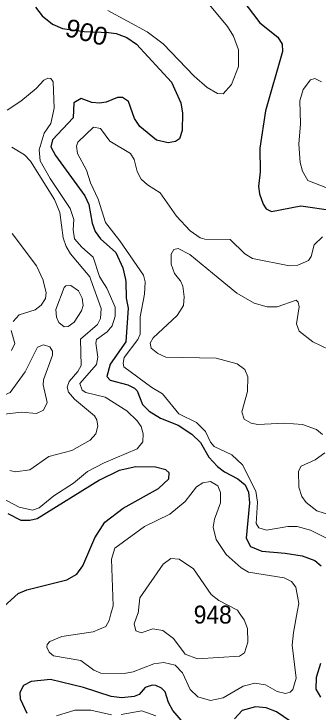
# Model space of a CAD drawing. Extents: x 473.9 to 500, y 7733.1 to 7760.8.
# Drawn here: x 486.645 to 488.002, y 7749.235 to 7752.349 of the extents above; entities that cross this region are included whole.
import ezdxf
from ezdxf.enums import TextEntityAlignment as Align

# ---------------------------------------------------------------- set-up
doc = ezdxf.new("R2010")
doc.units = 0
doc.header["$LTSCALE"] = 0.032
doc.layers.add('1', color=7, linetype='Continuous', lineweight=25)
doc.layers.add('2', color=7, linetype='Continuous', lineweight=13)
doc.layers.add('21', color=7, linetype='Continuous')
doc.layers.add('61', color=7, linetype='Continuous')

msp = doc.modelspace()

# ---------------------------------------------------------------- linework, layer by layer
at = {"layer": '1'}
for points in [[(487.6624, 7752.4168), (487.7421, 7752.3088), (487.8228, 7752.245), (487.8424, 7752.2149), (487.8435, 7752.1809), (487.7675, 7751.9168), (487.7416, 7751.7506), (487.7432, 7751.6445), (487.7368, 7751.5795), (487.7412, 7751.546), (487.7566, 7751.5003), (487.7708, 7751.4799), (487.7935, 7751.4682), (487.9246, 7751.4925), (488.0693, 7751.4728)], [(486.7413, 7752.3792), (486.7715, 7752.3404)], [(486.7715, 7752.3404), (486.8178, 7752.3038), (486.8624, 7752.2837), (486.9592, 7752.27), (487.0341, 7752.2684), (487.0669, 7752.2669), (487.1013, 7752.2616), (487.1494, 7752.2436), (487.1916, 7752.2137), (487.3483, 7752.0443), (487.3892, 7751.9522), (487.3974, 7751.9065), (487.396, 7751.8291), (487.384, 7751.7921), (487.3653, 7751.7804), (487.3331, 7751.774), (487.281, 7751.7862), (487.2073, 7751.8476), (487.1834, 7751.883), (487.1561, 7751.9579), (487.1295, 7751.9762), (487.1077, 7751.9757), (487.0572, 7751.9558), (487.0267, 7751.9508), (486.9933, 7751.9535), (486.9448, 7751.9715), (486.9128, 7751.953), (486.9101, 7751.885), (486.8175, 7751.7871), (486.8101, 7751.7566), (486.8313, 7751.7171), (486.9619, 7751.5371), (486.9793, 7751.4997), (486.9944, 7751.416), (487.0074, 7751.378), (487.0312, 7751.3459), (487.0992, 7751.2845), (487.1316, 7751.217), (487.1427, 7751.1649), (487.145, 7751.154), (487.1466, 7751.0807), (487.1546, 7751.0366), (487.1447, 7750.8865), (487.0745, 7750.7865), (487.06, 7750.7324), (487.0744, 7750.716), (487.1527, 7750.694), (487.1835, 7750.6796), (487.195, 7750.6677), (487.218, 7750.6067), (487.2485, 7750.5774), (487.2991, 7750.5462), (487.3771, 7750.5153), (487.4395, 7750.4738), (487.4778, 7750.4368), (487.5141, 7750.3725), (487.5532, 7750.3299), (487.5851, 7750.3061), (487.644, 7750.2749), (487.6765, 7750.2486), (487.6914, 7750.2158), (487.6958, 7750.1679), (487.6811, 7750.0111), (487.701, 7749.973), (487.7509, 7749.9518), (487.8557, 7749.9439), (487.931, 7749.9316), (487.9871, 7749.9104), (488.0151, 7749.8877)], [(486.6007, 7749.7061), (486.6635, 7749.7638), (486.7032, 7749.7805), (486.8809, 7749.8243), (486.9263, 7749.8499), (486.9528, 7749.887), (487.0065, 7750.0119), (487.0514, 7750.0819), (487.1322, 7750.1441), (487.2902, 7750.2322), (487.3363, 7750.2745), (487.337, 7750.3026), (487.3233, 7750.3147), (487.2769, 7750.3266), (487.1884, 7750.3282), (487.1141, 7750.3124), (487.0273, 7750.2693), (486.7481, 7750.0969), (486.7167, 7750.0894), (486.6774, 7750.0889), (486.6192, 7750.1185)], [(488.0124, 7749.4521), (487.9937, 7749.3883), (487.9924, 7749.3375), (488.0129, 7749.3011)], [(487.3201, 7749.325), (487.3042, 7749.3409), (487.2789, 7749.3539), (487.2613, 7749.3543), (487.2311, 7749.3439), (487.2032, 7749.3134), (487.1819, 7749.304), (487.1261, 7749.2984), (487.0795, 7749.3043), (486.9558, 7749.344), (486.8089, 7749.3803), (486.7227, 7749.3716), (486.6884, 7749.3525), (486.6715, 7749.3218), (486.6724, 7749.2932), (486.7028, 7749.2292)], [(487.401, 7749.1867), (487.3545, 7749.2411), (487.3351, 7749.2771), (487.3201, 7749.325)], [(487.9893, 7749.1176), (487.8171, 7749.2364), (487.7705, 7749.2541), (487.7232, 7749.2574), (487.663, 7749.2419), (487.6289, 7749.2052)]]:
    msp.add_lwpolyline(points, dxfattribs=at)
at = {"layer": '2'}
for points in [[(487.0643, 7752.3643), (487.2396, 7752.2688), (487.3115, 7752.2161), (487.4499, 7752.072), (487.5069, 7752.0209), (487.553, 7751.9937), (487.5784, 7751.9923), (487.6153, 7752.0339), (487.6475, 7752.114), (487.6468, 7752.1892), (487.6245, 7752.2492), (487.5973, 7752.293), (487.5029, 7752.4077)], [(486.6157, 7751.9203), (486.6753, 7751.9597), (486.7444, 7752.0166), (486.7788, 7752.0532), (486.796, 7752.0625), (486.8103, 7752.0615), (486.8201, 7752.0464), (486.825, 7751.9282), (486.8102, 7751.8596), (486.7795, 7751.8171), (486.7583, 7751.7421), (486.7616, 7751.6943), (486.8063, 7751.6155), (486.8965, 7751.4805), (486.9126, 7751.4317), (486.9095, 7751.386), (486.9157, 7751.3459), (486.9481, 7751.3082), (486.9986, 7751.2641), (487.0274, 7751.1772), (487.036, 7751.1631), (487.0589, 7751.1252), (487.0967, 7751.0409), (487.0975, 7751.0008), (487.0833, 7750.9584), (487.0607, 7750.9316), (487.0142, 7750.8964), (487.0109, 7750.8798), (487.0197, 7750.8177), (487.0136, 7750.7853), (486.9394, 7750.7001), (486.9489, 7750.6713), (486.9654, 7750.6597), (487.0523, 7750.64), (487.1491, 7750.5791), (487.1952, 7750.5345), (487.2127, 7750.5089), (487.2224, 7750.4753), (487.2195, 7750.4398), (487.1948, 7750.4084)], [(488.0366, 7751.5745), (487.9558, 7751.6067), (487.9323, 7751.648), (487.9216, 7751.6857), (487.9161, 7751.7688), (487.9242, 7751.8594), (487.9211, 7751.9608), (487.9355, 7752.0116), (487.968, 7752.0551), (487.9871, 7752.0607), (488.0166, 7752.046)], [(488.0218, 7751.3546), (487.9852, 7751.3183), (487.971, 7751.2668), (487.9595, 7751.2488), (487.9115, 7751.2278), (487.8745, 7751.2255), (487.71, 7751.2575), (487.6757, 7751.2788), (487.6098, 7751.3422), (487.4972, 7751.3446), (487.4756, 7751.3499), (487.4307, 7751.3813), (487.371, 7751.4474), (487.2978, 7751.5503), (487.2403, 7751.5862), (487.2121, 7751.6119), (487.1945, 7751.6455), (487.1819, 7751.6992), (487.1655, 7751.7268), (487.0737, 7751.782), (487.0315, 7751.8373), (487.0008, 7751.8439), (486.9296, 7751.7765), (486.9239, 7751.7599), (486.9292, 7751.7259), (486.9689, 7751.6525), (486.9871, 7751.5952)], [(486.6271, 7750.3125), (486.6524, 7750.3058), (486.7156, 7750.3155), (486.8014, 7750.3751), (486.9028, 7750.402), (486.9851, 7750.447), (487.0112, 7750.4763), (487.0199, 7750.5108), (487.0152, 7750.5391), (487.005, 7750.5566), (486.9149, 7750.6307), (486.889, 7750.6614), (486.8831, 7750.6843), (486.8909, 7750.71), (486.9307, 7750.7533), (486.9451, 7750.7803), (486.9425, 7750.8988), (487.0184, 7750.9632), (487.0321, 7750.9907), (487.0348, 7751.035), (486.9887, 7751.1623), (486.9836, 7751.1764), (486.8982, 7751.2795), (486.8782, 7751.3118), (486.8651, 7751.3497), (486.8499, 7751.4627), (486.8266, 7751.5206), (486.7191, 7751.6922), (486.6922, 7751.7205), (486.6357, 7751.7544)], [(486.9871, 7751.5952), (487.0206, 7751.5233), (487.0531, 7751.4183), (487.1181, 7751.3362), (487.2231, 7751.1839), (487.2278, 7751.1663), (487.231, 7751.1541), (487.2279, 7751.0983), (487.2089, 7750.9975), (487.2083, 7750.921), (487.1976, 7750.8967), (487.1376, 7750.8161), (487.1322, 7750.7912), (487.1356, 7750.7746), (487.2599, 7750.6827), (487.3079, 7750.6543), (487.3815, 7750.5646), (487.4602, 7750.5268), (487.5004, 7750.4867), (487.5216, 7750.439), (487.5387, 7750.4196), (487.6178, 7750.3821), (487.6652, 7750.3371), (487.725, 7750.2202), (487.732, 7750.171), (487.7256, 7750.0758), (487.7379, 7750.0563), (487.7716, 7750.0469), (487.867, 7750.0629), (487.9088, 7750.0629), (487.9677, 7750.0462), (488.036, 7750.0126)], [(486.6372, 7751.37), (486.7462, 7751.2248), (486.7757, 7751.1609), (486.7762, 7751.1587), (486.7889, 7751.1063), (486.7856, 7751.0795), (486.7669, 7751.0492), (486.7396, 7751.0295), (486.6678, 7751.0064), (486.6412, 7750.9767)], [(488.0215, 7750.4724), (487.9952, 7750.495), (487.9319, 7750.5171), (487.8525, 7750.5236), (487.7325, 7750.5173), (487.7042, 7750.524), (487.6716, 7750.5412), (487.6622, 7750.5746), (487.6877, 7750.6651), (487.6893, 7750.7295), (487.6755, 7750.7633), (487.6405, 7750.7889), (487.5481, 7750.8139), (487.3235, 7750.8173), (487.2869, 7750.8336), (487.2569, 7750.8586), (487.2535, 7750.8804), (487.2661, 7750.9042), (487.373, 7751.0033), (487.4018, 7751.0478), (487.4047, 7751.087), (487.3982, 7751.1347), (487.3878, 7751.1588), (487.3798, 7751.1689), (487.3619, 7751.1915), (487.3465, 7751.2329), (487.3471, 7751.2779), (487.3586, 7751.2979), (487.3778, 7751.3024), (487.4296, 7751.2762), (487.5559, 7751.1719), (487.6389, 7751.1034), (487.717, 7751.0586), (487.7748, 7751.0431), (487.8199, 7751.0431), (487.904, 7751.0723), (487.9126, 7751.0639), (487.9175, 7751.042), (487.9064, 7750.9659), (487.9178, 7750.9339), (487.9789, 7750.8865), (488.09, 7750.8334)], [(486.6321, 7750.9364), (486.6496, 7750.8785), (486.6348, 7750.848)], [(487.1948, 7750.4084), (487.0475, 7750.3462), (486.9741, 7750.3078), (486.9108, 7750.2553), (486.823, 7750.1993), (486.7571, 7750.1454), (486.7281, 7750.1355), (486.6678, 7750.1485), (486.563, 7750.2037), (486.4527, 7750.3122), (486.3765, 7750.3667), (486.2912, 7750.3863), (486.2585, 7750.4055), (486.2486, 7750.4557), (486.236, 7750.4803), (486.1481, 7750.543), (486.106, 7750.619), (486.0678, 7750.6493)], [(488.1276, 7750.091), (487.9962, 7750.1331), (487.9496, 7750.1694), (487.9301, 7750.1967), (487.9159, 7750.2386), (487.9145, 7750.3099), (487.9259, 7750.332), (487.9886, 7750.3602), (488.0328, 7750.3915)], [(487.0807, 7749.222), (486.9885, 7749.2429), (486.9168, 7749.243), (486.835, 7749.2172)], [(487.2779, 7749.2182), (487.2164, 7749.2396), (487.1231, 7749.2234)]]:
    msp.add_lwpolyline(points, dxfattribs=at)
for points in [[(486.8871, 7750.955), (486.9143, 7750.9746), (486.9469, 7751.0248), (486.9536, 7751.049), (486.9496, 7751.0816), (486.9335, 7751.1138), (486.8989, 7751.1372), (486.8774, 7751.1354), (486.87, 7751.1284), (486.8323, 7751.0302), (486.8349, 7750.997), (486.8462, 7750.9725), (486.8697, 7750.9537)], [(486.6955, 7750.7519), (486.7508, 7750.8629), (486.7768, 7750.8726), (486.8058, 7750.8634), (486.8167, 7750.8451), (486.8167, 7750.8265), (486.7774, 7750.7172), (486.776, 7750.6941), (486.7927, 7750.6164), (486.7768, 7750.5813), (486.7462, 7750.5663), (486.6792, 7750.5728), (486.6015, 7750.5631), (486.5543, 7750.5669), (486.5379, 7750.5747), (486.5256, 7750.5969), (486.5297, 7750.6123), (486.5558, 7750.6295), (486.6288, 7750.6604)], [(487.4317, 7749.3349), (487.3965, 7749.41), (487.3644, 7749.4439), (487.3133, 7749.4552), (487.2686, 7749.4495), (487.1778, 7749.4138), (487.1376, 7749.4067), (487.0329, 7749.4087), (487.0017, 7749.421), (486.943, 7749.4652), (486.8213, 7749.486), (486.8017, 7749.5026), (486.7914, 7749.5236), (486.7935, 7749.5357), (486.8054, 7749.5489), (486.8596, 7749.5717), (486.9982, 7749.5933), (487.0545, 7749.6164), (487.0703, 7749.6426), (487.078, 7749.6727), (487.0872, 7749.709), (487.08, 7749.9174), (487.0958, 7749.9665), (487.2283, 7750.0624), (487.34, 7750.1173), (487.4091, 7750.1736), (487.4595, 7750.239), (487.4881, 7750.2577), (487.5227, 7750.2639), (487.5544, 7750.2444), (487.5674, 7750.214), (487.567, 7750.1678), (487.5399, 7750.0959), (487.5342, 7750.0595), (487.5476, 7750.0047), (487.5923, 7749.9383), (487.6592, 7749.8787), (487.6918, 7749.8588), (487.8509, 7749.833), (487.8831, 7749.8169), (487.9032, 7749.792), (487.916, 7749.7196), (487.9087, 7749.6805), (487.8918, 7749.59), (487.8871, 7749.5329), (487.904, 7749.3857), (487.8887, 7749.3354), (487.8781, 7749.3238), (487.8563, 7749.3181), (487.8199, 7749.3268), (487.7674, 7749.3567), (487.7202, 7749.3633), (487.6677, 7749.3498), (487.5791, 7749.2985), (487.5219, 7749.2863), (487.4651, 7749.3032)], [(487.6515, 7749.4841), (487.674, 7749.4994), (487.6885, 7749.5459), (487.6877, 7749.6077), (487.6726, 7749.6469), (487.6503, 7749.678), (487.6425, 7749.689), (487.5591, 7749.7329), (487.5258, 7749.7593), (487.4458, 7749.8731), (487.3819, 7749.9164), (487.3454, 7749.9195), (487.3114, 7749.8941), (487.2062, 7749.744), (487.1987, 7749.6741), (487.1986, 7749.6738), (487.181, 7749.6282), (487.1884, 7749.5974), (487.2125, 7749.5879), (487.2653, 7749.606), (487.3088, 7749.5982), (487.3565, 7749.5636), (487.4085, 7749.493), (487.4645, 7749.4729)]]:
    msp.add_lwpolyline(points, close=True, dxfattribs=at)

# ---------------------------------------------------------------- texts
at = {"layer": '21', "width": 0.95}
msp.add_text('948', height=0.08, dxfattribs=at).set_placement((487.4473, 7749.6296))
at = {"layer": '61', "width": 1.05}
msp.add_text('900', height=0.08, rotation=345.556, dxfattribs=at).set_placement((486.9592, 7752.2287), align=Align.CENTER)

doc.saveas('drawing.dxf')
